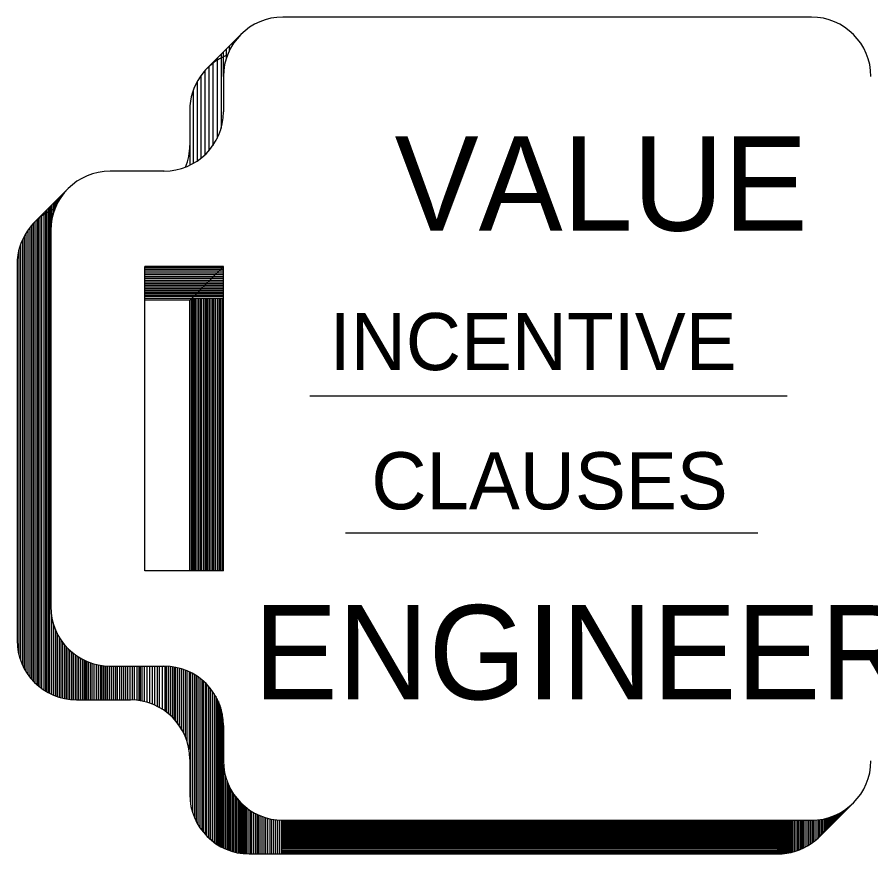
# Model space of a CAD drawing. Extents: x 44742.55 to 44745.38, y 44738.95 to 44741.13.
# Drawn here: x 44742.6864 to 44742.7441, y 44739.0118 to 44739.0683 of the extents above; entities that cross this region are included whole.
import ezdxf

# ---------------------------------------------------------------- set-up
doc = ezdxf.new("R2010")
doc.units = 0
doc.layers.add('Level 2', color=7, linetype='Continuous')
doc.layers.add('Level 7', color=7, linetype='Continuous')

msp = doc.modelspace()

# ---------------------------------------------------------------- linework, layer by layer
at = {"layer": 'Level 2'}
for p, q in [((44742.69924843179, 44739.06488061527), (44742.70152157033, 44739.067153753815)), ((44742.70075047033, 44739.066061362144), (44742.70075047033, 44739.06638265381)), ((44742.70095127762, 44739.06642281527), (44742.70095127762, 44739.0665834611)), ((44742.701119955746, 44739.066679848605), (44742.701119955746, 44739.066752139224)), ((44742.700188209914, 44739.06582039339), (44742.700188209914, 44739.06081627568)), ((44742.70034885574, 44739.06431032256), (44742.70034885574, 44739.06598103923)), ((44742.70054163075, 44739.06553926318), (44742.70054163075, 44739.06617381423)), ((44742.699625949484, 44739.06525813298), (44742.699625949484, 44739.0596435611)), ((44742.69991511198, 44739.065547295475), (44742.69991511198, 44739.0601254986)), ((44742.69908778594, 44739.064703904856), (44742.69908778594, 44739.05901704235)), ((44742.699352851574, 44739.06498503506), (44742.699352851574, 44739.05929014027)), ((44742.69856568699, 44739.06395690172), (44742.69856568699, 44739.05859936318)), ((44742.69881468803, 44739.06435851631), (44742.69881468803, 44739.058784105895)), ((44742.69829258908, 44739.06333841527), (44742.69829258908, 44739.05843871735)), ((44742.6980757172, 44739.06203718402), (44742.6980757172, 44739.05832626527)), ((44742.687585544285, 44739.05447879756), (44742.68985868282, 44739.05675193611)), ((44742.68897513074, 44739.055402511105), (44742.68897513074, 44739.05586838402)), ((44742.689055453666, 44739.05558725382), (44742.689055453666, 44739.05594870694)), ((44742.689127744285, 44739.055739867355), (44742.689127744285, 44739.05602099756)), ((44742.689208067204, 44739.055892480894), (44742.689208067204, 44739.05610132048)), ((44742.689288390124, 44739.05602099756), (44742.689288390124, 44739.05618164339)), ((44742.68936871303, 44739.05614951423), (44742.68936871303, 44739.05626196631)), ((44742.68944903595, 44739.05626196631), (44742.68944903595, 44739.05634228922)), ((44742.68842090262, 44739.05531415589), (44742.68842090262, 44739.02277534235)), ((44742.6885253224, 44739.05541857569), (44742.6885253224, 44739.022719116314)), ((44742.68859761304, 44739.05549086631), (44742.68859761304, 44739.022678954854)), ((44742.68868596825, 44739.05390850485), (44742.68868596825, 44739.055579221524)), ((44742.68877432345, 44739.054743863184), (44742.68877432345, 44739.05566757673)), ((44742.68888677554, 44739.055161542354), (44742.68888677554, 44739.05578002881)), ((44742.68783454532, 44739.054727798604), (44742.68783454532, 44739.02318498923)), ((44742.687938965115, 44739.0548322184), (44742.687938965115, 44739.02310466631)), ((44742.68806748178, 44739.05496073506), (44742.68806748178, 44739.02300827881)), ((44742.68820403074, 44739.05509728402), (44742.68820403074, 44739.02291189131)), ((44742.688316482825, 44739.05520973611), (44742.688316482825, 44739.022839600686)), ((44742.68727228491, 44739.054117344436), (44742.68727228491, 44739.02377134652)), ((44742.687384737, 44739.054253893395), (44742.687384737, 44739.02363479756)), ((44742.687489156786, 44739.054374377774), (44742.687489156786, 44739.02351431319)), ((44742.68760160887, 44739.05448682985), (44742.68760160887, 44739.02340186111)), ((44742.68773815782, 44739.0546314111), (44742.68773815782, 44739.023273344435)), ((44742.68687870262, 44739.05351492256), (44742.68687870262, 44739.02437376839)), ((44742.68700721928, 44739.053739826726), (44742.68700721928, 44739.02414886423)), ((44742.687135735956, 44739.053932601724), (44742.687135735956, 44739.02395608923)), ((44742.68664576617, 44739.05298479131), (44742.68664576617, 44739.02490389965)), ((44742.68677428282, 44739.05329805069), (44742.68677428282, 44739.02459064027)), ((44742.68652528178, 44739.05257514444), (44742.68652528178, 44739.02531354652)), ((44742.6864128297, 44739.05163536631), (44742.6864128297, 44739.02625332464)), ((44742.70034885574, 44739.05139439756), (44742.69503147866, 44739.05139439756)), ((44742.70034885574, 44739.05128997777), (44742.69503147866, 44739.05128997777)), ((44742.70034885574, 44739.05149881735), (44742.6980757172, 44739.04922567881)), ((44742.70034885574, 44739.051169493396), (44742.69503147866, 44739.051169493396)), ((44742.70034885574, 44739.051049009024), (44742.69503147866, 44739.051049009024)), ((44742.70034885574, 44739.05092049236), (44742.69503147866, 44739.05092049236)), ((44742.70034885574, 44739.05080000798), (44742.69503147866, 44739.05080000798)), ((44742.70034885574, 44739.0506795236), (44742.69503147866, 44739.0506795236)), ((44742.70034885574, 44739.05055100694), (44742.69503147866, 44739.05055100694)), ((44742.70034885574, 44739.050438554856), (44742.69503147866, 44739.050438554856)), ((44742.70034885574, 44739.050318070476), (44742.69503147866, 44739.050318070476)), ((44742.70034885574, 44739.050197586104), (44742.69503147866, 44739.050197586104)), ((44742.70034885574, 44739.05008513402), (44742.69503147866, 44739.05008513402)), ((44742.70034885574, 44739.04997268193), (44742.69503147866, 44739.04997268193)), ((44742.70034885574, 44739.04987629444), (44742.69503147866, 44739.04987629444)), ((44742.70034885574, 44739.04975581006), (44742.69503147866, 44739.04975581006)), ((44742.70034885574, 44739.04965942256), (44742.69503147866, 44739.04965942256)), ((44742.70034885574, 44739.04955500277), (44742.69503147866, 44739.04955500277)), ((44742.70034885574, 44739.04945861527), (44742.69503147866, 44739.04945861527)), ((44742.70034885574, 44739.0493381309), (44742.69503147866, 44739.0493381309)), ((44742.6980757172, 44739.04922567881), (44742.69503147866, 44739.04922567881)), ((44742.6980757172, 44739.03093615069), (44742.6980757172, 44739.04922567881)), ((44742.698188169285, 44739.03093615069), (44742.698188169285, 44739.0493381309)), ((44742.69827652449, 44739.03093615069), (44742.69827652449, 44739.0493381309)), ((44742.698372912, 44739.03093615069), (44742.698372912, 44739.0493381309)), ((44742.698453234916, 44739.03093615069), (44742.698453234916, 44739.0493381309)), ((44742.69857371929, 44739.03093615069), (44742.69857371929, 44739.0493381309)), ((44742.69867813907, 44739.03093615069), (44742.69867813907, 44739.0493381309)), ((44742.69879059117, 44739.03093615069), (44742.69879059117, 44739.0493381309)), ((44742.698870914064, 44739.03093615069), (44742.698870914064, 44739.0493381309)), ((44742.698999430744, 44739.03093615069), (44742.698999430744, 44739.0493381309)), ((44742.69910385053, 44739.03093615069), (44742.69910385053, 44739.0493381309)), ((44742.69919220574, 44739.03093615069), (44742.69919220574, 44739.0493381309)), ((44742.69929662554, 44739.03093615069), (44742.69929662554, 44739.0493381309)), ((44742.69940104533, 44739.03093615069), (44742.69940104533, 44739.0493381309)), ((44742.6995215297, 44739.03093615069), (44742.6995215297, 44739.0493381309)), ((44742.699617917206, 44739.03093615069), (44742.699617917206, 44739.0493381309)), ((44742.699714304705, 44739.03093615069), (44742.699714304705, 44739.0493381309)), ((44742.699834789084, 44739.03093615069), (44742.699834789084, 44739.0493381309)), ((44742.699955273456, 44739.03093615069), (44742.699955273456, 44739.0493381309)), ((44742.70007575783, 44739.03093615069), (44742.70007575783, 44739.0493381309)), ((44742.70015608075, 44739.03093615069), (44742.70015608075, 44739.0493381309)), ((44742.70026050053, 44739.03093615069), (44742.70026050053, 44739.0493381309)), ((44742.68874219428, 44739.02785978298), (44742.68874219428, 44739.02260666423)), ((44742.688870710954, 44739.02732161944), (44742.688870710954, 44739.02255043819)), ((44742.688991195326, 44739.02699229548), (44742.688991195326, 44739.022502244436)), ((44742.6891116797, 44739.02672722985), (44742.6891116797, 44739.022462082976)), ((44742.68925626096, 44739.02646216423), (44742.68925626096, 44739.02241388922)), ((44742.68936068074, 44739.026301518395), (44742.68936068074, 44739.02238176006)), ((44742.689465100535, 44739.02614890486), (44742.689465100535, 44739.02235766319)), ((44742.68960164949, 44739.02597219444), (44742.68960164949, 44739.022325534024)), ((44742.68971410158, 44739.02584367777), (44742.68971410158, 44739.022301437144)), ((44742.68983458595, 44739.0257151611), (44742.68983458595, 44739.022285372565)), ((44742.689955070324, 44739.02559467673), (44742.689955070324, 44739.022261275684)), ((44742.690075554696, 44739.025490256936), (44742.690075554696, 44739.02225324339)), ((44742.69018800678, 44739.02539386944), (44742.69018800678, 44739.0222452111)), ((44742.69032455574, 44739.025289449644), (44742.69032455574, 44739.02223717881)), ((44742.69044504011, 44739.02520109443), (44742.69044504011, 44739.02223717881)), ((44742.690565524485, 44739.02512880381), (44742.690565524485, 44739.02223717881)), ((44742.690686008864, 44739.02505651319), (44742.690686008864, 44739.02223717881)), ((44742.690830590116, 44739.02497619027), (44742.690830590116, 44739.02223717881)), ((44742.6909350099, 44739.02491996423), (44742.6909350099, 44739.02223717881)), ((44742.69099926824, 44739.02488783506), (44742.69099926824, 44739.02223717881)), ((44742.69110368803, 44739.02483964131), (44742.69110368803, 44739.02223717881)), ((44742.691208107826, 44739.024799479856), (44742.691208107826, 44739.02223717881)), ((44742.69133662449, 44739.0247512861), (44742.69133662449, 44739.02223717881)), ((44742.691465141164, 44739.02470309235), (44742.691465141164, 44739.02223717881)), ((44742.69158562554, 44739.02467096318), (44742.69158562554, 44739.02223717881)), ((44742.69174627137, 44739.02462276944), (44742.69174627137, 44739.02223717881)), ((44742.69189085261, 44739.02459064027), (44742.69189085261, 44739.02223717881)), ((44742.692011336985, 44739.0245665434), (44742.692011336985, 44739.02223717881)), ((44742.6920996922, 44739.024558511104), (44742.6920996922, 44739.02223717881)), ((44742.692220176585, 44739.02454244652), (44742.692220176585, 44739.02223717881)), ((44742.69232459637, 44739.02452638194), (44742.69232459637, 44739.02223717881)), ((44742.692412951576, 44739.024518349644), (44742.692412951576, 44739.02223717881)), ((44742.69252540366, 44739.02451031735), (44742.69252540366, 44739.02223717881)), ((44742.69265392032, 44739.02451031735), (44742.69265392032, 44739.02223717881)), ((44742.6927744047, 44739.02451031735), (44742.6927744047, 44739.02223717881)), ((44742.692910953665, 44739.02451031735), (44742.692910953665, 44739.02223717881)), ((44742.693047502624, 44739.02451031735), (44742.693047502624, 44739.02223717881)), ((44742.693167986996, 44739.02451031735), (44742.693167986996, 44739.02223717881)), ((44742.69332863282, 44739.02451031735), (44742.69332863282, 44739.02223717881)), ((44742.69346518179, 44739.02451031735), (44742.69346518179, 44739.02223717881)), ((44742.693585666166, 44739.02451031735), (44742.693585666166, 44739.02223717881)), ((44742.693722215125, 44739.02451031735), (44742.693722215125, 44739.02223717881)), ((44742.69387482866, 44739.02451031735), (44742.69387482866, 44739.02223717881)), ((44742.6940194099, 44739.02451031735), (44742.6940194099, 44739.02223717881)), ((44742.69417202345, 44739.02451031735), (44742.69417202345, 44739.02223717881)), ((44742.69432463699, 44739.02451031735), (44742.69432463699, 44739.02223717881)), ((44742.69450134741, 44739.02451031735), (44742.69450134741, 44739.02221308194)), ((44742.69462183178, 44739.02451031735), (44742.69462183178, 44739.02219701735)), ((44742.69472625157, 44739.02451031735), (44742.69472625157, 44739.02218095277)), ((44742.69483067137, 44739.02451031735), (44742.69483067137, 44739.02216488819)), ((44742.6949993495, 44739.02451031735), (44742.6949993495, 44739.022124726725)), ((44742.695176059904, 44739.02451031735), (44742.695176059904, 44739.02207653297)), ((44742.695360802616, 44739.02451031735), (44742.695360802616, 44739.02202030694)), ((44742.695537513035, 44739.02451031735), (44742.695537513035, 44739.0219560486)), ((44742.69569012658, 44739.02451031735), (44742.69569012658, 44739.02189179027)), ((44742.69586683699, 44739.02451031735), (44742.69586683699, 44739.021811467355)), ((44742.69600338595, 44739.02451031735), (44742.69600338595, 44739.02173917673)), ((44742.69621222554, 44739.02451031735), (44742.69621222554, 44739.021610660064)), ((44742.69638090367, 44739.02451031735), (44742.69638090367, 44739.021498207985)), ((44742.69646925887, 44739.02451031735), (44742.69646925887, 44739.021433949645)), ((44742.69662187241, 44739.02451031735), (44742.69662187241, 44739.02131346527)), ((44742.696742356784, 44739.02448622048), (44742.696742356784, 44739.02120904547)), ((44742.69687087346, 44739.0244701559), (44742.69687087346, 44739.0210885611)), ((44742.69699135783, 44739.02445409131), (44742.69699135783, 44739.02096807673)), ((44742.697079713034, 44739.02443802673), (44742.697079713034, 44739.02087168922)), ((44742.697216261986, 44739.02441392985), (44742.697216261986, 44739.0207030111)), ((44742.697352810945, 44739.024381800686), (44742.697352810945, 44739.02051826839)), ((44742.697497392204, 44739.024341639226), (44742.697497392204, 44739.02029336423)), ((44742.69763394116, 44739.02429344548), (44742.69763394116, 44739.02005239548)), ((44742.69775442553, 44739.02425328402), (44742.69775442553, 44739.01979536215)), ((44742.69788294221, 44739.02419705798), (44742.69788294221, 44739.0194499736)), ((44742.69801949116, 44739.02414083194), (44742.69801949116, 44739.01888771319)), ((44742.69812391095, 44739.02409263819), (44742.69812391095, 44739.01523302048)), ((44742.698252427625, 44739.02402034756), (44742.698252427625, 44739.01467076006)), ((44742.698380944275, 44739.023948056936), (44742.698380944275, 44739.01431733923)), ((44742.69850142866, 44739.02387576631), (44742.69850142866, 44739.014052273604)), ((44742.69862191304, 44739.02379544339), (44742.69862191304, 44739.01382736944)), ((44742.69874239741, 44739.023707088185), (44742.69874239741, 44739.013634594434)), ((44742.69887894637, 44739.02360266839), (44742.69887894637, 44739.013441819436)), ((44742.69898336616, 44739.02351431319), (44742.69898336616, 44739.01330527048)), ((44742.69910385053, 44739.02340186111), (44742.69910385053, 44739.013168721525)), ((44742.699208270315, 44739.02329744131), (44742.699208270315, 44739.01305626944)), ((44742.699336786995, 44739.02316089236), (44742.699336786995, 44739.01292775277)), ((44742.69945727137, 44739.023016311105), (44742.69945727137, 44739.01282333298)), ((44742.69959382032, 44739.022839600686), (44742.69959382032, 44739.0127028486)), ((44742.69972233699, 44739.02264682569), (44742.69972233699, 44739.0126064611)), ((44742.69982675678, 44739.02247814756), (44742.69982675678, 44739.01253417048)), ((44742.690428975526, 44739.02223717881), (44742.69405957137, 44739.02223717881)), ((44742.69992314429, 44739.02229340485), (44742.69992314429, 44739.012469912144)), ((44742.70000346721, 44739.022124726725), (44742.70000346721, 44739.01242171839)), ((44742.700107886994, 44739.021867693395), (44742.700107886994, 44739.012357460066)), ((44742.7001962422, 44739.02159459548), (44742.7001962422, 44739.01230926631)), ((44742.70026853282, 44739.0212893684), (44742.70026853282, 44739.01226910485)), ((44742.6980757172, 44739.01822103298), (44742.6980757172, 44739.015851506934)), ((44742.70035688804, 44739.01786761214), (44742.70035688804, 44739.01222894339)), ((44742.70046934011, 44739.0171447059), (44742.70046934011, 44739.01218074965)), ((44742.70057375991, 44739.01679931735), (44742.70057375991, 44739.0121325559)), ((44742.70066211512, 44739.016566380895), (44742.70066211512, 44739.01210042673)), ((44742.700758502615, 44739.01635754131), (44742.700758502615, 44739.01206026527)), ((44742.70083882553, 44739.01620492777), (44742.70083882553, 44739.012036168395)), ((44742.70095127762, 44739.016012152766), (44742.70095127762, 44739.01200403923)), ((44742.701055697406, 44739.015851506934), (44742.701055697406, 44739.01197191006)), ((44742.7011681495, 44739.0156908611), (44742.7011681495, 44739.011939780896)), ((44742.70124847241, 44739.0155944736), (44742.70124847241, 44739.01192371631)), ((44742.70136092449, 44739.015457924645), (44742.70136092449, 44739.011899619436)), ((44742.70142518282, 44739.01538563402), (44742.70142518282, 44739.01189158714)), ((44742.70151353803, 44739.01529727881), (44742.70151353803, 44739.01187552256)), ((44742.701609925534, 44739.015200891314), (44742.701609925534, 44739.01186749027)), ((44742.70168221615, 44739.01513663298), (44742.70168221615, 44739.011859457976)), ((44742.701730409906, 44739.01509647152), (44742.701730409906, 44739.01185142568)), ((44742.70178663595, 44739.01504827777), (44742.70178663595, 44739.0118433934)), ((44742.701874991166, 44739.01497598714), (44742.701874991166, 44739.0118433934)), ((44742.70198744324, 44739.014887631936), (44742.70198744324, 44739.0118433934)), ((44742.74063079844, 44739.01300807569), (44742.74290393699, 44739.015281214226)), ((44742.74247019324, 44739.01484747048), (44742.74247019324, 44739.01491172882)), ((44742.70211595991, 44739.01479927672), (44742.70211595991, 44739.0118433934)), ((44742.702228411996, 44739.014726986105), (44742.702228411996, 44739.0118433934)), ((44742.702356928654, 44739.014646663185), (44742.702356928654, 44739.0118433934)), ((44742.70247741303, 44739.01458240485), (44742.70247741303, 44739.0118433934)), ((44742.70259789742, 44739.01451814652), (44742.70259789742, 44739.0118433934)), ((44742.702694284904, 44739.01446995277), (44742.702694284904, 44739.0118433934)), ((44742.70280673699, 44739.01442175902), (44742.70280673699, 44739.0118433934)), ((44742.70293525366, 44739.014373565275), (44742.70293525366, 44739.0118433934)), ((44742.70306377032, 44739.01432537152), (44742.70306377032, 44739.0118433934)), ((44742.741257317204, 44739.013634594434), (44742.741257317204, 44739.01429324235)), ((44742.74133764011, 44739.01371491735), (44742.74133764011, 44739.01431733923)), ((44742.74140993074, 44739.01378720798), (44742.74140993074, 44739.0143414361)), ((44742.741490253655, 44739.0138675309), (44742.741490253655, 44739.014373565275)), ((44742.74153844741, 44739.013915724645), (44742.74153844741, 44739.014389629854)), ((44742.741634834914, 44739.014012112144), (44742.741634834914, 44739.014429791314)), ((44742.74170712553, 44739.01408440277), (44742.74170712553, 44739.01446192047)), ((44742.74178744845, 44739.01416472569), (44742.74178744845, 44739.01450208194)), ((44742.74187580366, 44739.014253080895), (44742.74187580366, 44739.0145422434)), ((44742.741948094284, 44739.01432537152), (44742.741948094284, 44739.01458240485)), ((44742.74202038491, 44739.01439766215), (44742.74202038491, 44739.01462256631)), ((44742.74209267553, 44739.01446995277), (44742.74209267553, 44739.01466272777)), ((44742.742172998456, 44739.014550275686), (44742.742172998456, 44739.014710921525)), ((44742.742253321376, 44739.0146305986), (44742.742253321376, 44739.01475911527)), ((44742.742325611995, 44739.01470288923), (44742.742325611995, 44739.01480730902)), ((44742.74239790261, 44739.01477517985), (44742.74239790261, 44739.01485550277)), ((44742.703192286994, 44739.01428521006), (44742.703192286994, 44739.0118433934)), ((44742.70332883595, 44739.0142450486), (44742.70332883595, 44739.0118433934)), ((44742.703473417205, 44739.01420488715), (44742.703473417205, 44739.0118433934)), ((44742.703585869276, 44739.01418079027), (44742.703585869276, 44739.0118433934)), ((44742.703730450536, 44739.014156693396), (44742.703730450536, 44739.0118433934)), ((44742.7038589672, 44739.01414062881), (44742.7038589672, 44739.0118433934)), ((44742.70398748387, 44739.01412456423), (44742.70398748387, 44739.0118433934)), ((44742.704140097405, 44739.01411653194), (44742.704140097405, 44739.0118433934)), ((44742.70426861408, 44739.01410849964), (44742.70426861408, 44739.0118433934)), ((44742.70426861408, 44739.014052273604), (44742.7377873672, 44739.014052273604)), ((44742.70426861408, 44739.014012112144), (44742.7377873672, 44739.014012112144)), ((44742.70426861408, 44739.013971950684), (44742.7377873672, 44739.013971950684)), ((44742.70426861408, 44739.013915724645), (44742.7377873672, 44739.013915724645)), ((44742.70426861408, 44739.01385146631), (44742.7377873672, 44739.01385146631)), ((44742.70426861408, 44739.013779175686), (44742.7377873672, 44739.013779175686)), ((44742.7377873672, 44739.0118353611), (44742.7377873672, 44739.01410849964)), ((44742.737875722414, 44739.0118353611), (44742.737875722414, 44739.01410849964)), ((44742.73793998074, 44739.0118353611), (44742.73793998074, 44739.01410849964)), ((44742.738004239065, 44739.0118433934), (44742.738004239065, 44739.01410849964)), ((44742.738108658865, 44739.01185142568), (44742.738108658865, 44739.01410849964)), ((44742.73818898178, 44739.011859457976), (44742.73818898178, 44739.01410849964)), ((44742.73828536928, 44739.01186749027), (44742.73828536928, 44739.01410849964)), ((44742.7383656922, 44739.01187552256), (44742.7383656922, 44739.01410849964)), ((44742.73845404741, 44739.01189158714), (44742.73845404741, 44739.01410849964)), ((44742.73852633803, 44739.01190765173), (44742.73852633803, 44739.01410849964)), ((44742.738622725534, 44739.01192371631), (44742.738622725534, 44739.01410849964)), ((44742.73871108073, 44739.011939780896), (44742.73871108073, 44739.01410849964)), ((44742.73879943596, 44739.011963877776), (44742.73879943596, 44739.01410849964)), ((44742.73891188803, 44739.011996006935), (44742.73891188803, 44739.01410849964)), ((44742.7390323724, 44739.012036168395), (44742.7390323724, 44739.01410849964)), ((44742.73912875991, 44739.01206829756), (44742.73912875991, 44739.01410849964)), ((44742.73922514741, 44739.01210042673), (44742.73922514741, 44739.01410849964)), ((44742.7393295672, 44739.01214058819), (44742.7393295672, 44739.01410849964)), ((44742.739433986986, 44739.01218878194), (44742.739433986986, 44739.01410849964)), ((44742.7395223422, 44739.01222894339), (44742.7395223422, 44739.01410849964)), ((44742.739642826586, 44739.01229320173), (44742.739642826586, 44739.01410849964)), ((44742.73976331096, 44739.012357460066), (44742.73976331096, 44739.01410849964)), ((44742.739875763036, 44739.01242171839), (44742.739875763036, 44739.01410849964)), ((44742.739988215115, 44739.012494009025), (44742.739988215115, 44739.01410849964)), ((44742.7401006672, 44739.01256629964), (44742.7401006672, 44739.01410849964)), ((44742.74020508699, 44739.01264662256), (44742.74020508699, 44739.01410849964)), ((44742.74031753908, 44739.01273497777), (44742.74031753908, 44739.01410849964)), ((44742.74043802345, 44739.012831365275), (44742.74043802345, 44739.01412456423)), ((44742.74055047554, 44739.01293578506), (44742.74055047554, 44739.01414062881)), ((44742.74064686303, 44739.013024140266), (44742.74064686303, 44739.0141486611)), ((44742.740751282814, 44739.013128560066), (44742.740751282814, 44739.01416472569)), ((44742.74083160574, 44739.01320888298), (44742.74083160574, 44739.01418079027)), ((44742.74092799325, 44739.01330527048), (44742.74092799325, 44739.01420488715)), ((44742.74100831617, 44739.0133855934), (44742.74100831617, 44739.01422095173)), ((44742.741096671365, 44739.0134739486), (44742.741096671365, 44739.0142450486)), ((44742.74119305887, 44739.0135703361), (44742.74119305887, 44739.01426914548)), ((44742.70426861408, 44739.01370688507), (44742.7377873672, 44739.01370688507)), ((44742.70426861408, 44739.01364262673), (44742.7377873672, 44739.01364262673)), ((44742.70426861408, 44739.0135703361), (44742.7377873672, 44739.0135703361)), ((44742.70426861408, 44739.01349804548), (44742.7377873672, 44739.01349804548)), ((44742.70426861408, 44739.01342575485), (44742.7377873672, 44739.01342575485)), ((44742.70426861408, 44739.01335346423), (44742.7377873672, 44739.01335346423)), ((44742.70426861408, 44739.013281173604), (44742.7377873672, 44739.013281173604)), ((44742.70426861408, 44739.01321691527), (44742.7377873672, 44739.01321691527)), ((44742.70426861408, 44739.013144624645), (44742.7377873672, 44739.013144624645)), ((44742.70426861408, 44739.01308036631), (44742.7377873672, 44739.01308036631)), ((44742.70426861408, 44739.01301610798), (44742.7377873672, 44739.01301610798)), ((44742.70426861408, 44739.01294381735), (44742.7377873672, 44739.01294381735)), ((44742.70426861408, 44739.01287152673), (44742.7377873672, 44739.01287152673)), ((44742.70426861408, 44739.012791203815), (44742.7377873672, 44739.012791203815)), ((44742.70426861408, 44739.012710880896), (44742.7377873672, 44739.012710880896)), ((44742.70426861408, 44739.01263055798), (44742.7377873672, 44739.01263055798)), ((44742.70426861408, 44739.01255826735), (44742.7377873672, 44739.01255826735)), ((44742.70426861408, 44739.012469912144), (44742.7377873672, 44739.012469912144)), ((44742.70426861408, 44739.012389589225), (44742.7377873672, 44739.012389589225)), ((44742.70426861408, 44739.01230123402), (44742.7377873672, 44739.01230123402)), ((44742.70426861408, 44739.012212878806), (44742.7377873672, 44739.012212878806)), ((44742.70426861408, 44739.012116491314), (44742.7377873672, 44739.012116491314)), ((44742.70426861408, 44739.0120281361), (44742.7377873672, 44739.0120281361)), ((44742.702091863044, 44739.0118353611), (44742.7377873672, 44739.0118353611)), ((44742.70426861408, 44739.011939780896), (44742.7377873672, 44739.011939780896))]:
    msp.add_line(p, q, dxfattribs=at)
for centre, radius, start, end in [((44742.702086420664, 44739.06203786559), 0.004016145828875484, 111.40791388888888, 180), ((44742.69405412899, 44739.05966833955), 0.004016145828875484, 338.59208611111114, 5.684341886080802e-14), ((44742.69042353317, 44739.05163604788), 0.004016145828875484, 111.40791388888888, 180), ((44742.69042353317, 44739.02625400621), 0.004016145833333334, 180, 270), ((44742.69405412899, 44739.01822171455), 0.004016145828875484, 0, 90), ((44742.702086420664, 44739.0158521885), 0.004016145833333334, 180, 270), ((44742.73778192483, 44739.0158521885), 0.004016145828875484, 270, 338.59208611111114)]:
    msp.add_arc(centre, radius, start, end, dxfattribs=at)
at = {"layer": 'Level 7'}
for p, q in [((44742.740060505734, 44739.0683264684), (44742.70436500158, 44739.0683264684)), ((44742.70034885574, 44739.06431032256), (44742.70034885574, 44739.06194079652)), ((44742.696332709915, 44739.05792465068), (44742.69270211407, 44739.05792465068)), ((44742.68868596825, 44739.05390850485), (44742.68868596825, 44739.02852646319)), ((44742.70034885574, 44739.05149881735), (44742.69503147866, 44739.05149881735)), ((44742.69503147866, 44739.03093615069), (44742.69503147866, 44739.05149881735)), ((44742.70034885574, 44739.03093615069), (44742.70034885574, 44739.05149881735)), ((44742.70617226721, 44739.04276771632), (44742.73842191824, 44739.04276771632)), ((44742.708598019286, 44739.03351451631), (44742.73642990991, 44739.03351451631)), ((44742.70034885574, 44739.03093615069), (44742.69503147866, 44739.03093615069)), ((44742.69270211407, 44739.02451031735), (44742.696332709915, 44739.02451031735)), ((44742.70034885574, 44739.02049417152), (44742.70034885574, 44739.018124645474)), ((44742.70436500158, 44739.01410849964), (44742.740060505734, 44739.01410849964))]:
    msp.add_line(p, q, dxfattribs=at)
for centre, radius, start, end in [((44742.704359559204, 44739.06431100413), 0.004016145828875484, 90, 180), ((44742.740055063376, 44739.06431100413), 0.004016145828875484, 0, 90), ((44742.696327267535, 44739.06194147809), 0.004016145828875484, 270, 0), ((44742.69269667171, 44739.05390918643), 0.004016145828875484, 90, 180), ((44742.69269667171, 44739.02852714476), 0.004016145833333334, 180, 270), ((44742.696327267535, 44739.02049485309), 0.004016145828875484, 0, 90), ((44742.704359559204, 44739.01812532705), 0.004016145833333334, 180, 270), ((44742.740055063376, 44739.01812532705), 0.004016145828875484, 270, 0)]:
    msp.add_arc(centre, radius, start, end, dxfattribs=at)

# ---------------------------------------------------------------- texts
at = {"layer": 'Level 2'}
for s, height, p in [('VALUE', 0.006361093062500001, (44742.71190732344, 44739.05390850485)), ('INCENTIVE', 0.0038553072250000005, (44742.707505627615, 44739.04449465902)), ('CLAUSES', 0.0038553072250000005, (44742.71033299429, 44739.03509687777)), ('ENGINEERING', 0.006361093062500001, (44742.70238102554, 44739.02226930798))]:
    msp.add_text(s, height=height, dxfattribs=at).set_placement(p)

doc.saveas('drawing.dxf')
